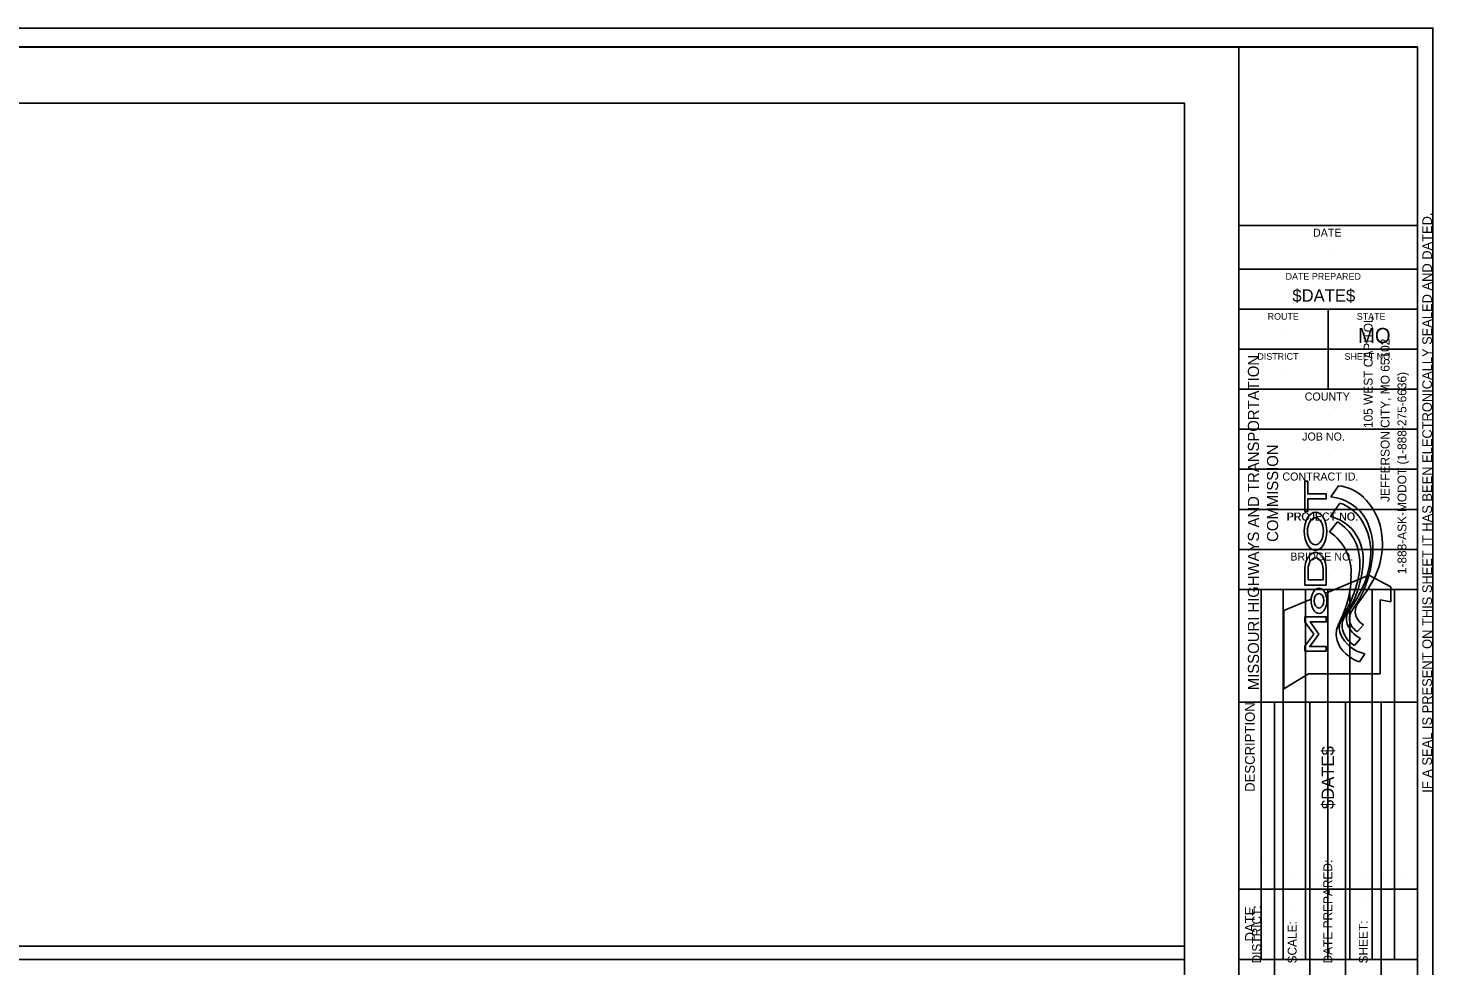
# Model space of a CAD drawing. Extents: x 0 to 31.6, y 0 to 20.8.
# Drawn here: x 15.8 to 31.6, y 10.25 to 20.8 of the extents above; entities that cross this region are included whole.
import ezdxf

# ---------------------------------------------------------------- set-up
doc = ezdxf.new("R2010")
doc.units = 0
for name, color, linetype in [('Border-Border', 7, 'Continuous'), ('Border-Full plan shape', 7, 'Continuous'), ('Border-Full profile shape', 7, 'Continuous'), ('Border-Plan bottom shape', 7, 'Continuous'), ('Border-Plan top shape', 7, 'Continuous'), ('Border-Plotting block', 7, 'Continuous'), ('Border-Title block - Final Plans Consultant Manual Seal', 7, 'Continuous'), ('Border-Title block - Final Plans Electronic Seal', 7, 'Continuous'), ('Border-Title block - Location Survey Electronic Seal', 7, 'Continuous'), ('Border-Xsection shape', 7, 'Continuous')]:
    doc.layers.add(name, color=color, linetype=linetype)

msp = doc.modelspace()

# ---------------------------------------------------------------- linework, layer by layer
at = {"layer": 'Border-Border'}
for p, q in [((0.175, 20.587), (31.425, 20.587)), ((31.425, 20.587), (31.425, 0.212))]:
    msp.add_line(p, q, dxfattribs=at)
at = {"layer": 'Border-Full plan shape'}
msp.add_lwpolyline([(0.806, 19.956), (28.806, 19.956), (28.806, 0.844), (0.806, 0.844)], close=True, dxfattribs=at)
at = {"layer": 'Border-Full profile shape'}
msp.add_lwpolyline([(0.806, 19.956), (28.806, 19.956), (28.806, 0.844), (0.806, 0.844)], close=True, dxfattribs=at)
at = {"layer": 'Border-Plan bottom shape'}
msp.add_lwpolyline([(0.806, 10.325), (28.806, 10.325), (28.806, 0.844), (0.806, 0.844)], close=True, dxfattribs=at)
at = {"layer": 'Border-Plan top shape'}
msp.add_lwpolyline([(0.806, 19.956), (28.806, 19.956), (28.806, 10.475), (0.806, 10.475)], close=True, dxfattribs=at)
at = {"layer": 'Border-Plotting block'}
msp.add_lwpolyline([(0, 0), (31.6, 0), (31.6, 20.8), (0, 20.8)], close=True, dxfattribs=at)
at = {"layer": 'Border-Title block - Final Plans Consultant Manual Seal'}
for p, q in [((29.417, 20.588), (31.425, 20.588)), ((29.417, 20.587), (29.417, 0.212)), ((29.417, 18.58), (31.425, 18.58)), ((30.421, 18.285), (30.421, 18.285)), ((29.417, 18.088), (31.425, 18.088)), ((30.421, 17.793), (30.421, 17.793)), ((29.417, 17.638), (31.425, 17.638)), ((30.421, 16.738), (30.421, 17.638)), ((29.919, 17.343), (29.919, 17.343)), ((30.923, 17.343), (30.923, 17.343)), ((29.417, 17.188), (31.425, 17.188)), ((29.919, 16.895), (29.919, 16.895)), ((30.923, 16.895), (30.923, 16.895)), ((29.417, 16.738), (31.425, 16.738)), ((30.421, 16.443), (30.421, 16.443)), ((29.417, 16.288), (31.425, 16.288)), ((30.421, 15.993), (30.421, 15.993)), ((29.417, 15.838), (31.425, 15.838)), ((30.421, 15.543), (30.421, 15.543)), ((29.417, 15.388), (31.425, 15.388)), ((30.421, 15.093), (30.421, 15.093)), ((29.417, 14.938), (31.425, 14.938)), ((30.421, 14.643), (30.421, 14.643)), ((29.417, 14.488), (31.425, 14.488)), ((29.667, 14.488), (29.667, 10.327)), ((29.917, 14.488), (29.917, 10.327)), ((30.167, 14.488), (30.167, 10.327)), ((30.417, 14.488), (30.417, 10.327)), ((30.667, 14.488), (30.667, 10.327)), ((30.917, 14.488), (30.917, 10.327)), ((31.167, 14.488), (31.167, 10.327)), ((29.417, 11.117), (31.425, 11.117)), ((29.417, 10.327), (31.425, 10.327))]:
    msp.add_line(p, q, dxfattribs=at)
at = {"layer": 'Border-Title block - Final Plans Electronic Seal'}
for p, q in [((29.417, 20.587), (29.417, 0.212)), ((29.417, 18.088), (31.425, 18.088)), ((30.421, 17.793), (30.421, 17.793)), ((29.417, 17.638), (31.425, 17.638)), ((30.421, 16.738), (30.421, 17.638)), ((29.919, 17.343), (29.919, 17.343)), ((30.923, 17.343), (30.923, 17.343)), ((29.417, 17.188), (31.425, 17.188)), ((29.919, 16.895), (29.919, 16.895)), ((30.923, 16.895), (30.923, 16.895)), ((29.417, 16.738), (31.425, 16.738)), ((30.421, 16.443), (30.421, 16.443)), ((29.417, 16.288), (31.425, 16.288)), ((30.421, 15.993), (30.421, 15.993)), ((29.417, 15.838), (31.425, 15.838)), ((30.421, 15.543), (30.421, 15.543)), ((29.417, 15.388), (31.425, 15.388)), ((30.421, 15.093), (30.421, 15.093)), ((29.417, 14.938), (31.425, 14.938)), ((30.421, 14.643), (30.421, 14.643)), ((29.417, 14.488), (31.425, 14.488)), ((29.667, 14.488), (29.667, 10.327)), ((29.917, 14.488), (29.917, 10.327)), ((30.167, 14.488), (30.167, 10.327)), ((30.417, 14.488), (30.417, 10.327)), ((30.667, 14.488), (30.667, 10.327)), ((30.917, 14.488), (30.917, 10.327)), ((31.167, 14.488), (31.167, 10.327)), ((29.792, 11.297), (29.792, 11.297)), ((29.792, 11.297), (29.792, 11.297)), ((30.042, 11.297), (30.042, 11.297)), ((30.042, 11.297), (30.042, 11.297)), ((30.292, 11.297), (30.292, 11.297)), ((30.292, 11.297), (30.292, 11.297)), ((30.542, 11.297), (30.542, 11.297)), ((30.542, 11.297), (30.542, 11.297)), ((30.792, 11.297), (30.792, 11.297)), ((30.792, 11.297), (30.792, 11.297)), ((31.042, 11.297), (31.042, 11.297)), ((31.042, 11.297), (31.042, 11.297)), ((31.296, 11.297), (31.296, 11.297)), ((31.296, 11.297), (31.296, 11.297)), ((29.417, 11.117), (31.425, 11.117)), ((29.417, 10.327), (31.425, 10.327)), ((29.792, 10.362), (29.792, 10.362)), ((29.792, 10.362), (29.792, 10.362)), ((30.042, 10.362), (30.042, 10.362)), ((30.042, 10.362), (30.042, 10.362)), ((30.292, 10.362), (30.292, 10.362)), ((30.292, 10.362), (30.292, 10.362)), ((30.542, 10.362), (30.542, 10.362)), ((30.542, 10.362), (30.542, 10.362)), ((30.792, 10.362), (30.792, 10.362)), ((30.792, 10.362), (30.792, 10.362)), ((31.042, 10.362), (31.042, 10.362)), ((31.042, 10.362), (31.042, 10.362)), ((31.296, 10.362), (31.296, 10.362)), ((31.296, 10.362), (31.296, 10.362))]:
    msp.add_line(p, q, dxfattribs=at)
msp.add_lwpolyline([(29.417, 20.587), (31.425, 20.587), (31.425, 18.088), (29.417, 18.088)], close=True, dxfattribs=at)
at = {"layer": 'Border-Title block - Location Survey Electronic Seal'}
for p, q in [((29.417, 20.587), (29.417, 0.212)), ((29.417, 18.088), (31.425, 18.088)), ((30.537, 15.653), (30.452, 15.528)), ((30.554, 15.458), (30.448, 15.307)), ((30.527, 15.246), (30.438, 15.135)), ((30.16, 14.707), (30.16, 14.534)), ((30.196, 14.594), (30.196, 14.707)), ((30.366, 14.707), (30.366, 14.594)), ((30.401, 14.534), (30.401, 14.707)), ((30.366, 14.594), (30.196, 14.594)), ((30.88, 14.647), (30.39, 14.443)), ((31.127, 14.517), (30.88, 14.647)), ((30.16, 14.534), (30.401, 14.534)), ((31.127, 14.346), (31.127, 14.517)), ((30.231, 14.377), (29.922, 14.249)), ((29.922, 14.249), (29.922, 13.37)), ((31.007, 13.54), (31.007, 14.371)), ((31.007, 14.371), (31.127, 14.346)), ((30.752, 14.013), (30.821, 14.089)), ((30.719, 13.855), (30.786, 13.935)), ((30.773, 13.672), (30.833, 13.764)), ((29.922, 13.37), (30.2, 13.54)), ((30.2, 13.54), (31.007, 13.54)), ((29.417, 13.22), (31.425, 13.22)), ((29.817, 13.22), (29.817, 7.22)), ((30.217, 13.22), (30.217, 7.22)), ((30.617, 13.22), (30.617, 7.22)), ((31.017, 13.22), (31.017, 7.22)), ((29.617, 11.414), (29.617, 11.414)), ((30.017, 10.921), (30.017, 10.921)), ((30.817, 10.95), (30.817, 10.95))]:
    msp.add_line(p, q, dxfattribs=at)
for points in [[(29.417, 20.587), (31.425, 20.587), (31.425, 18.088), (29.417, 18.088)], [(30.16, 15.362), (30.16, 15.706), (30.193, 15.706), (30.193, 15.561), (30.401, 15.561), (30.401, 15.506), (30.193, 15.506), (30.193, 15.362)], [(30.401, 13.794), (30.159, 13.794), (30.159, 13.849), (30.259, 13.985), (30.16, 14.124), (30.16, 14.18), (30.401, 14.18), (30.401, 14.122), (30.219, 14.122), (30.316, 13.985), (30.215, 13.845), (30.401, 13.845)]]:
    msp.add_lwpolyline(points, close=True, dxfattribs=at)
for centre, radius, start, end in [((30.495, 15.189), 0.466, 45.1693, 84.902), ((30.408, 15.023), 0.507, 28.5725, 84.9889), ((30.329, 15.019), 0.703, 15.8221, 45.3322), ((30.395, 14.999), 0.486, 35.4806, 70.8474), ((30.336, 14.844), 0.477, 37.8205, 76.3964), ((30.245, 14.787), 0.539, 29.2666, 58.4191), ((30.246, 14.916), 0.655, 351.9272, 33.854), ((30.192, 14.946), 0.734, 356.2526, 25.8037), ((30.171, 15.001), 0.861, 331.4589, 14.0852), ((30.126, 14.677), 0.554, 55.7274, 55.7276), ((30.126, 14.677), 0.554, 356.1033, 55.7272), ((30.285, 14.82), 0.532, 351.8718, 36.464), ((30.152, 14.776), 0.627, 355.2048, 25.9837), ((29.659, 14.99), 1.269, 339.2778, 355.8465), ((29.624, 14.863), 1.194, 330.8019, 354.3058), ((29.694, 14.828), 1.088, 338.3366, 354.4662), ((29.853, 14.937), 1.048, 334.3097, 353.8237), ((29.663, 14.633), 1.016, 341.469, 0.3416), ((30.017, 14.82), 0.874, 328.3334, 341.428), ((29.009, 15.659), 2.196, 323.2547, 330.8755), ((28.696, 15.2), 2.152, 330.8271, 338.9455), ((28.929, 15.429), 2.094, 325.3377, 333.1413), ((28.593, 15.004), 2.148, 334.3727, 341.1665), ((31.133, 13.94), 0.578, 143.8762, 156.8714), ((30.795, 14.153), 0.167, 149.4043, 197.7638), ((30.814, 14.159), 0.153, 150.2552, 210.6413), ((33.478, 12.556), 3.262, 146.4094, 149.0393), ((30.904, 14.245), 0.177, 174.7527, 241.8661), ((30.912, 14.225), 0.188, 140.188, 168.8506), ((30.749, 13.985), 0.237, 157.7092, 198.1728), ((30.72, 14.057), 0.173, 147.0199, 203.0239), ((30.779, 14.078), 0.2, 153.2735, 205.15), ((30.942, 14.225), 0.33, 202.0629, 241.7201), ((30.852, 14.185), 0.199, 211.4954, 239.6897), ((30.788, 13.982), 0.273, 195.0361, 226.9912), ((30.903, 14.126), 0.368, 201.7288, 258.9961), ((30.858, 14.097), 0.279, 201.8104, 240.1114), ((30.951, 14.138), 0.499, 225.4988, 249.0787)]:
    msp.add_arc(centre, radius, start, end, dxfattribs=at)
for centre, major_axis, ratio in [((30.279, 15.141), (0, 0.214), 0.595517), ((30.279, 15.141), (0, -0.153), 0.589579), ((30.319, 14.36), (0, 0.142), 0.623747), ((30.319, 14.36), (0, 0.0823), 0.65252)]:
    msp.add_ellipse(centre, major_axis=major_axis, ratio=ratio, dxfattribs=at)
for centre, major_axis, ratio in [((30.28, 14.707), (0, -0.196), 0.614143), ((30.281, 14.707), (0, -0.137), 0.62091)]:
    msp.add_ellipse(centre, major_axis=major_axis, ratio=ratio, start_param=1.570796, end_param=4.712389, dxfattribs=at)
at = {"layer": 'Border-Xsection shape'}
msp.add_lwpolyline([(29.417, 0.212), (0.175, 0.212), (0.175, 20.588), (29.417, 20.588)], close=True, dxfattribs=at)

# ---------------------------------------------------------------- texts
at = {"layer": 'Border-Border'}
msp.add_text('IF A SEAL IS PRESENT ON THIS SHEET IT HAS BEEN ELECTRONICALLY SEALED AND DATED.  ', height=0.10827, rotation=90, dxfattribs=at).set_placement((31.589, 12.201))
at = {"layer": 'Border-Title block - Final Plans Consultant Manual Seal'}
for s, height, p in [('DATE', 0.09, (30.251, 18.454)), ('DATE PREPARED', 0.075, (29.943, 17.97)), ('ROUTE', 0.075, (29.741, 17.52)), ('STATE', 0.075, (30.744, 17.52)), ('MO', 0.17, (30.758, 17.258)), ('DISTRICT', 0.075, (29.626, 17.07)), ('SHEET NO.', 0.075, (30.606, 17.07)), ('COUNTY', 0.09, (30.158, 16.612)), ('JOB NO.', 0.09, (30.129, 16.162)), ('CONTRACT ID.', 0.09, (29.907, 15.712)), ('PROJECT NO.', 0.09, (29.952, 15.262)), ('PROJECT NO.', 0.08858, (29.959, 15.263)), ('BRIDGE NO.', 0.09, (29.996, 14.812))]:
    msp.add_text(s, height=height, dxfattribs=at).set_placement(p)
for s, height, p in [('DESCRIPTION', 0.11024, (29.597, 12.211)), ('DATE', 0.1102, (29.597, 10.528))]:
    msp.add_text(s, height=height, rotation=90, dxfattribs=at).set_placement(p)
at = {"layer": 'Border-Title block - Final Plans Electronic Seal'}
for s, height, p in [('DATE PREPARED', 0.075, (29.943, 17.97)), ('$DATE$', 0.14, (30.019, 17.723)), ('ROUTE', 0.075, (29.741, 17.52)), ('STATE', 0.075, (30.744, 17.52)), ('MO', 0.17, (30.758, 17.258)), ('DISTRICT', 0.075, (29.626, 17.07)), ('SHEET NO.', 0.075, (30.606, 17.07)), ('COUNTY', 0.09, (30.158, 16.612)), ('JOB NO.', 0.09, (30.129, 16.162)), ('CONTRACT ID.', 0.09, (29.907, 15.712)), ('PROJECT NO.', 0.08858, (29.959, 15.263)), ('PROJECT NO.', 0.08858, (29.959, 15.263)), ('BRIDGE NO.', 0.09, (29.996, 14.812))]:
    msp.add_text(s, height=height, dxfattribs=at).set_placement(p)
for s, height, p in [('DESCRIPTION', 0.11024, (29.597, 12.211)), ('DATE', 0.1102, (29.597, 10.528))]:
    msp.add_text(s, height=height, rotation=90, dxfattribs=at).set_placement(p)
at = {"layer": 'Border-Title block - Location Survey Electronic Seal'}
for s, height, p in [('105 WEST CAPITOL', 0.1, (30.922, 16.302)), ('JEFFERSON CITY, MO 65102', 0.1, (31.112, 15.472)), ('MISSOURI HIGHWAYS AND TRANSPORTATION', 0.125, (29.644, 13.354)), ('1-888-ASK-MODOT (1-888-275-6636)', 0.1, (31.302, 14.659)), ('COMMISSION', 0.125, (29.859, 15.022)), ('$DATE$', 0.14, (30.487, 12.017)), ('DATE PREPARED:', 0.1, (30.467, 10.281)), ('DISTRICT:', 0.1, (29.667, 10.281)), ('SCALE:', 0.1, (30.067, 10.281)), ('SHEET:', 0.1, (30.867, 10.281))]:
    msp.add_text(s, height=height, rotation=90, dxfattribs=at).set_placement(p)

doc.saveas('drawing.dxf')
